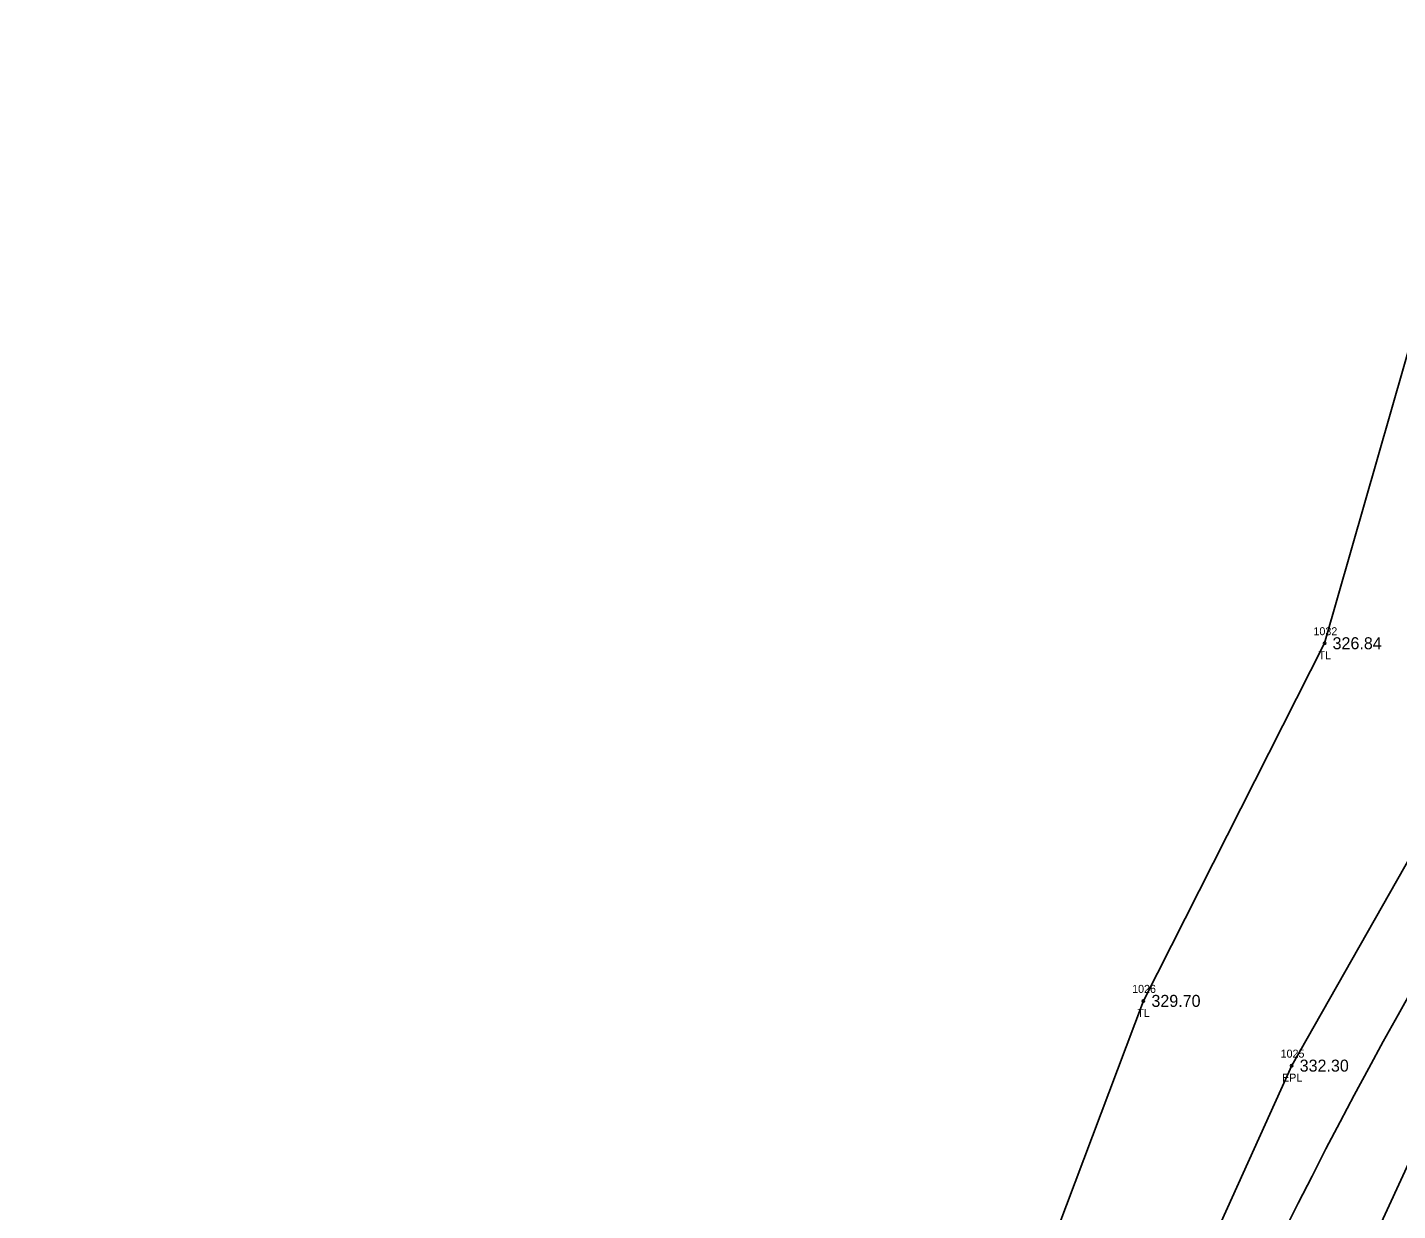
# Model space of a CAD drawing. Extents: x 2231119 to 2232595, y 1035731 to 1037094.
# Drawn here: x 2231141.6 to 2231312.8, y 1036161.6 to 1036309.5 of the extents above; entities that cross this region are included whole.
import ezdxf

# ---------------------------------------------------------------- set-up
doc = ezdxf.new("R2010")
doc.units = 0
for name, color, linetype in [('RD_EX_Road', 7, 'Continuous'), ('RD_EX_Road_txCode', 7, 'Continuous'), ('RD_EX_TX_Road_ELEV', 7, 'Continuous'), ('RD_EX_TX_VEG_ELEV', 7, 'Continuous'), ('RD_EX_VEG', 7, 'Continuous'), ('RD_EX_VEG_txCode', 7, 'Continuous'), ('RD_HC_Cl', 7, 'Continuous'), ('RD_SMD_Locator', 7, 'Continuous')]:
    doc.layers.add(name, color=color, linetype=linetype)

msp = doc.modelspace()

# ---------------------------------------------------------------- linework, layer by layer
at = {"layer": 'RD_EX_Road'}
for points in [[(2231158.42, 1035748.11), (2231188.37, 1035851.38), (2231216.59, 1035946.92), (2231244.77, 1036040.72), (2231278.59, 1036133.31), (2231299.55, 1036179.73), (2231323.11, 1036221.2), (2231350.7, 1036262.3), (2231381.59, 1036299.29), (2231415.97, 1036336.9), (2231452.94, 1036369.74), (2231498.19, 1036405.3), (2231537.2, 1036432.57), (2231541.46, 1036424.96)], [(2231176.43, 1035742.89), (2231206.61, 1035845.83), (2231234.19, 1035940.65), (2231261.92, 1036033.75), (2231294.68, 1036125.28), (2231316.11, 1036171.75), (2231338.19, 1036211.09), (2231363.83, 1036252.38), (2231394.08, 1036289.28), (2231427.67, 1036324.2), (2231464.37, 1036355.5), (2231508.96, 1036392.41), (2231546.55, 1036416.22), (2231541.46, 1036424.96)]]:
    msp.add_lwpolyline(points, dxfattribs=at)
at = {"layer": 'RD_EX_VEG'}
msp.add_lwpolyline([(2231141.61, 1035753.39), (2231172.54, 1035856.04), (2231200.09, 1035950.41), (2231226.19, 1036046.04), (2231262.9, 1036139.62), (2231281.03, 1036187.82), (2231303.66, 1036232.51), (2231318.61, 1036284.65), (2231353.84, 1036322.59), (2231394.02, 1036358.2), (2231443.85, 1036383.78)], dxfattribs=at)
at = {"layer": 'RD_HC_Cl'}
msp.add_arc((2231880.38, 1035870.33), 649.46, 120.68197, 163.7355, dxfattribs=at)
at = {"layer": 'RD_SMD_Locator'}
for centre in [(2231303.66, 1036232.51), (2231281.03, 1036187.82), (2231299.55, 1036179.73)]:
    msp.add_circle(centre, 0.15, dxfattribs=at)

# ---------------------------------------------------------------- texts
at = {"layer": 'RD_EX_Road_txCode'}
for s, p in [('1025', (2231298.17, 1036180.73)), ('EPL', (2231298.35, 1036177.73))]:
    msp.add_text(s, height=1, dxfattribs=at).set_placement(p)
at = {"layer": 'RD_EX_TX_Road_ELEV'}
msp.add_text('332.30', height=1.5, dxfattribs=at).set_placement((2231300.55, 1036178.98))
at = {"layer": 'RD_EX_TX_VEG_ELEV'}
for s, p in [('326.84', (2231304.66, 1036231.76)), ('329.70', (2231282.03, 1036187.07))]:
    msp.add_text(s, height=1.5, dxfattribs=at).set_placement(p)
at = {"layer": 'RD_EX_VEG_txCode'}
for s, p in [('1032', (2231302.27, 1036233.51)), ('TL', (2231302.89, 1036230.51)), ('1026', (2231279.62, 1036188.82)), ('TL', (2231280.26, 1036185.82))]:
    msp.add_text(s, height=1, dxfattribs=at).set_placement(p)

doc.saveas('drawing.dxf')
